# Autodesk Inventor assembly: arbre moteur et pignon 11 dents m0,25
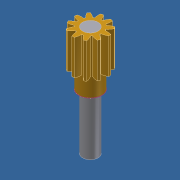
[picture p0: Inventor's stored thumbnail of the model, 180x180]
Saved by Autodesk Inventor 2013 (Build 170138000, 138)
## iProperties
Created: 2011-10
Part Number: arbre moteur et pignon 11 dents m0,25
Document SubType Name: Assembly
Designer: Laur
Author: Laur
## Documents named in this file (3)
- D:\_an13-14\FORMULAIRE_2014\Sujet E4 Poissy 2014\Modélisation_7970_shimano_2014\arbre moteur et pignon 11 dents m0,25.iam
- D:\_an13-14\FORMULAIRE_2014\Sujet E4 Poissy 2014\Modélisation_7970_shimano_2014\arbre moteur.ipt
- D:\_an13-14\FORMULAIRE_2014\Sujet E4 Poissy 2014\Modélisation_7970_shimano_2014\arbre moteur et pignon 11 dents m0,25\Design Accelerator\Engrenages cylindriques1.iam
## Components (2 placed, 2 different names)
1. arbre moteur:1 — Placage:1
2. Engrenages cylindriques:1 [sub-assembly] — Placage:1
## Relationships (1: Mate 1)
- Placage:1 [Mate]: arbre moteur:1 ↔ Engrenages cylindriques:1
